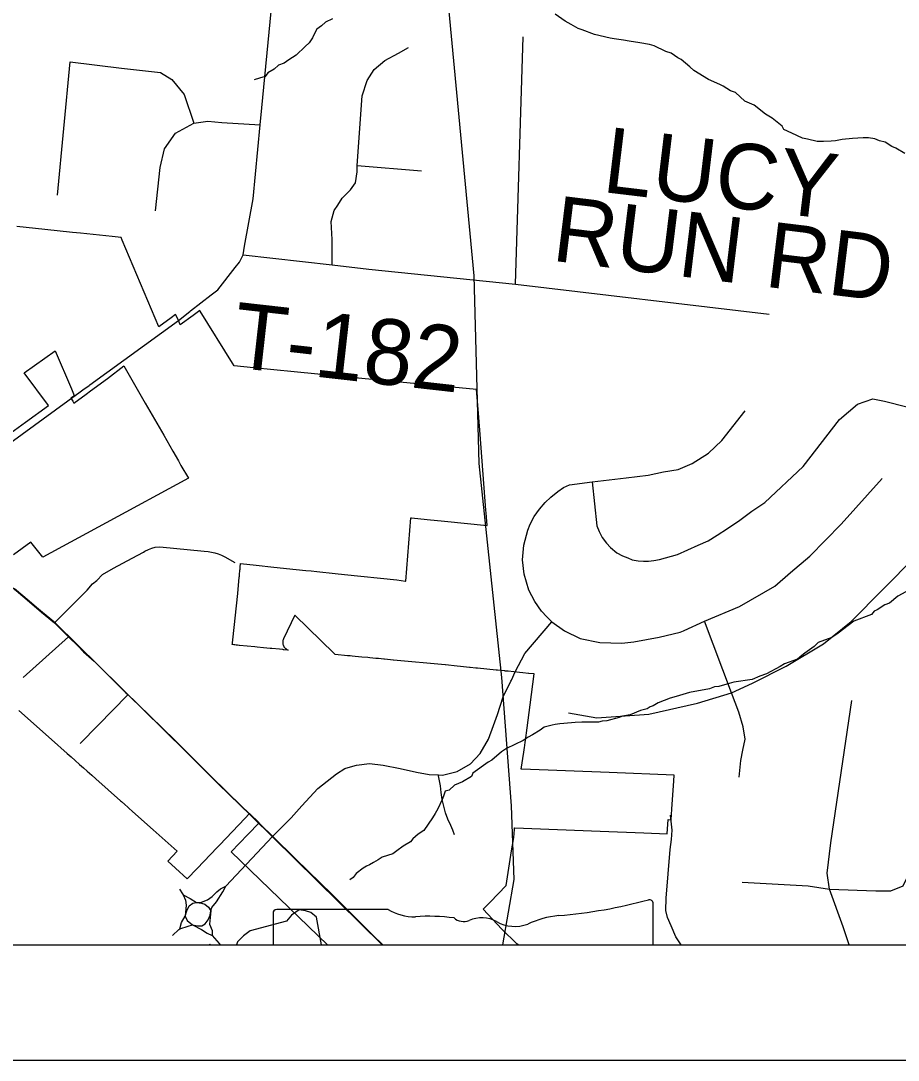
# Model space of a CAD drawing. Extents: x 0 to 34, y 0 to 22.
# Drawn here: x 2.613 to 3.374, y 14 to 14.902 of the extents above; entities that cross this region are included whole.
import ezdxf

# ---------------------------------------------------------------- set-up
doc = ezdxf.new("R2010")
doc.units = 0
for name, color, linetype in [('GM_X_City_Street', 7, 'Continuous'), ('GM_X_Corporation', 7, 'Continuous'), ('GM_X_County_Road', 7, 'Continuous'), ('GM_X_Minor_Lake', 7, 'Continuous'), ('GM_X_Minor_River', 7, 'Continuous'), ('GM_X_Rail_Line', 7, 'Continuous'), ('GM_X_State_Route', 7, 'Continuous'), ('GM_X_Township_Road', 7, 'Continuous'), ('GM_X_Township_Road_Text', 7, 'Continuous'), ('GM_X_Unincorporated_Text', 7, 'Continuous'), ('SH_Data', 7, 'Continuous')]:
    doc.layers.add(name, color=color, linetype=linetype)

msp = doc.modelspace()

# ---------------------------------------------------------------- linework, layer by layer
at = {"layer": 'GM_X_City_Street'}
msp.add_line((2.61532, 14.33202), (2.65464, 14.36727), dxfattribs=at)
at = {"layer": 'GM_X_Corporation'}
for points in [[(2.61152, 14.30346), (2.63996, 14.27817), (2.65355, 14.26609), (2.65684, 14.26316), (2.6603, 14.26009), (2.66421, 14.25661), (2.66766, 14.25354), (2.67075, 14.2508), (2.6747, 14.24729), (2.67838, 14.24401), (2.69964, 14.2251), (2.70042, 14.22441), (2.70331, 14.22184), (2.70601, 14.21944), (2.70685, 14.21869), (2.71009, 14.21581), (2.72812, 14.19978), (2.7488, 14.18138), (2.74083, 14.17279), (2.74737, 14.16663), (2.75738, 14.15721), (2.76615, 14.16639), (2.78359, 14.18464), (2.78381, 14.18487), (2.78565, 14.1868), (2.80756, 14.20972), (2.81153, 14.21387), (2.81155, 14.21389), (2.81981, 14.20583), (2.81979, 14.20581), (2.81001, 14.19576), (2.79551, 14.18084), (2.87906, 14.1), (3.04437, 14.1), (3.0434, 14.10096), (3.04339, 14.10096), (3.0304, 14.11377), (3.01404, 14.1311), (3.02007, 14.13723), (3.03408, 14.1515), (3.03881, 14.18174), (3.04062, 14.19331), (3.04116, 14.20016), (3.04127, 14.20152), (3.0416, 14.20151), (3.11549, 14.19866), (3.15335, 14.1972), (3.17359, 14.19642), (3.17439, 14.20882), (3.17722, 14.20863), (3.17782, 14.21782), (3.17941, 14.24237), (3.17973, 14.24733), (3.12346, 14.24951), (3.04773, 14.25243), (3.04701, 14.25246), (3.04936, 14.26732), (3.04999, 14.27129), (3.05021, 14.27311), (3.05022, 14.27319), (3.05032, 14.27397), (3.05043, 14.27491), (3.05045, 14.27512), (3.05052, 14.27564), (3.05055, 14.2759), (3.05055, 14.27591), (3.05055, 14.27591), (3.05074, 14.27734), (3.0522, 14.28836), (3.05482, 14.30828), (3.05836, 14.33505), (3.05762, 14.33512), (3.05358, 14.33553), (3.0535, 14.33554), (3.04841, 14.33606), (3.0455, 14.33635), (3.03587, 14.33734), (3.0358, 14.33735), (3.03578, 14.33735), (3.03576, 14.33736), (3.03574, 14.33736), (3.03568, 14.33736), (3.03565, 14.33737), (3.03561, 14.33737), (3.03461, 14.33747), (3.03406, 14.33753), (3.03343, 14.33759), (3.03296, 14.33764), (3.03227, 14.33771), (3.03227, 14.33771), (3.02999, 14.33794), (3.02654, 14.33829), (3.02527, 14.33842), (3.00906, 14.34007), (3.00779, 14.3402), (3.00283, 14.3407), (3.00238, 14.34075), (2.99458, 14.34154), (2.99456, 14.34154), (2.9917, 14.34192), (2.98139, 14.34288), (2.98102, 14.34292), (2.93642, 14.3471), (2.9363, 14.34711), (2.93607, 14.34713), (2.93375, 14.34735), (2.92856, 14.34783), (2.92851, 14.34784), (2.92805, 14.34788), (2.92343, 14.34832), (2.92094, 14.34855), (2.91594, 14.34902), (2.91417, 14.34918), (2.90879, 14.34969), (2.9031, 14.35022), (2.90048, 14.35047), (2.89884, 14.35062), (2.89846, 14.35066), (2.89845, 14.35066), (2.89821, 14.35068), (2.89736, 14.35076), (2.89714, 14.35078), (2.89642, 14.35085), (2.88578, 14.35184), (2.88491, 14.35269), (2.88489, 14.35271), (2.85074, 14.38596), (2.84102, 14.36558), (2.84087, 14.36523), (2.84073, 14.36488), (2.84062, 14.36452), (2.84052, 14.36415), (2.84044, 14.36378), (2.84038, 14.36341), (2.84034, 14.36303), (2.84032, 14.36265), (2.84032, 14.36227), (2.84034, 14.36189), (2.84039, 14.36152), (2.84045, 14.36114), (2.84053, 14.36077), (2.84063, 14.36041), (2.84074, 14.36005), (2.84088, 14.35969), (2.84104, 14.35935), (2.84121, 14.35901), (2.8414, 14.35868), (2.84161, 14.35837), (2.84184, 14.35806), (2.84208, 14.35777), (2.84233, 14.35749), (2.8426, 14.35722), (2.84286, 14.35699), (2.84289, 14.35697), (2.84289, 14.35697), (2.84318, 14.35674), (2.84349, 14.35651), (2.84381, 14.35631), (2.84442, 14.35598), (2.84511, 14.35566), (2.84505, 14.35566), (2.84126, 14.35603), (2.84122, 14.35604), (2.84112, 14.35605), (2.84105, 14.35605), (2.84054, 14.35611), (2.84049, 14.35611), (2.83754, 14.3564), (2.83749, 14.35641), (2.83094, 14.35705), (2.83089, 14.35706), (2.83087, 14.35706), (2.83081, 14.35706), (2.82956, 14.35719), (2.82952, 14.35719), (2.82375, 14.35776), (2.81826, 14.3583), (2.81616, 14.35851), (2.80288, 14.35982), (2.80288, 14.35982), (2.80287, 14.35982), (2.80284, 14.35982), (2.80282, 14.35982), (2.80265, 14.35984), (2.80261, 14.35984), (2.80124, 14.35998), (2.80119, 14.35998), (2.80076, 14.36003), (2.80071, 14.36003), (2.80038, 14.36006), (2.80034, 14.36007), (2.80009, 14.36009), (2.80005, 14.3601), (2.79892, 14.36021), (2.79887, 14.36021), (2.79846, 14.36025), (2.79842, 14.36026), (2.79822, 14.36028), (2.79817, 14.36028), (2.79787, 14.36031), (2.79782, 14.36031), (2.79658, 14.36044), (2.79658, 14.36048), (2.79659, 14.36056), (2.79669, 14.36152), (2.79671, 14.36166), (2.79671, 14.36167), (2.79671, 14.36169), (2.79687, 14.36321), (2.79693, 14.36378), (2.79702, 14.36464), (2.79702, 14.36466), (2.80127, 14.40482), (2.80264, 14.419), (2.80272, 14.4198), (2.80277, 14.42027), (2.80277, 14.42029), (2.80289, 14.42156), (2.80289, 14.42156), (2.80289, 14.42157), (2.8029, 14.42158), (2.80317, 14.42442), (2.80323, 14.42498), (2.80331, 14.42585), (2.80347, 14.42753), (2.80379, 14.4308), (2.81733, 14.42939), (2.83252, 14.4278), (2.85207, 14.42577), (2.86026, 14.4249), (2.86492, 14.42441), (2.86987, 14.42388), (2.88587, 14.42219), (2.89383, 14.42134), (2.93925, 14.41662), (2.9393, 14.41662), (2.9467, 14.41566), (2.94714, 14.4156), (2.94719, 14.4156), (2.95136, 14.47054), (2.95136, 14.47054), (2.9515, 14.47053), (2.95197, 14.47048), (2.95206, 14.47047), (2.96559, 14.46907), (2.98056, 14.46752), (3.01743, 14.4637), (3.01658, 14.47469), (3.0164, 14.47706), (3.01137, 14.54267), (3.00994, 14.56124), (3.00838, 14.58164), (2.92362, 14.58994), (2.85025, 14.59713), (2.81509, 14.60057), (2.79829, 14.60222), (2.79689, 14.60449), (2.76882, 14.64975), (2.76853, 14.65022), (2.76274, 14.64599), (2.75143, 14.63772), (2.74965, 14.64239), (2.74747, 14.64674), (2.74363, 14.64394), (2.7328, 14.63602), (2.70122, 14.71127), (2.70028, 14.71351), (2.69245, 14.71434), (2.66489, 14.71729), (2.65807, 14.71802), (2.63408, 14.72059), (2.60982, 14.72319)], [(2.59822, 14.53956), (2.61719, 14.55336), (2.63713, 14.56787), (2.61617, 14.59622), (2.64299, 14.61528), (2.64304, 14.61528), (2.65704, 14.58235), (2.65956, 14.57645), (2.6582, 14.57544), (2.65673, 14.57437), (2.6582, 14.57176), (2.65919, 14.57), (2.66981, 14.57774), (2.67356, 14.58047), (2.6736, 14.58047), (2.68843, 14.59129), (2.68848, 14.59129), (2.70246, 14.60232), (2.70263, 14.60242), (2.72119, 14.56999), (2.73713, 14.54213), (2.73714, 14.54211), (2.7451, 14.52821), (2.74988, 14.51986), (2.75211, 14.51596), (2.75849, 14.50481), (2.68721, 14.46601), (2.63243, 14.43625), (2.62189, 14.44944), (2.60692, 14.43841)], [(2.1, 14.1), (2.92709, 14.1), (2.91838, 14.10854), (2.88332, 14.1436), (2.85158, 14.17424), (2.83128, 14.19448), (2.78403, 14.24031), (2.74675, 14.27759), (2.70393, 14.3193), (2.67652, 14.34656), (2.66723, 14.35478), (2.66279, 14.35954), (2.6544, 14.3678), (2.64208, 14.37994), (2.63088, 14.38929), (2.62061, 14.39819), (2.60788, 14.40877)], [(2.60788, 14.40877), (2.62061, 14.39819), (2.63088, 14.38929), (2.64208, 14.37994), (2.6544, 14.3678), (2.66279, 14.35954), (2.66723, 14.35478), (2.67652, 14.34656), (2.70393, 14.3193), (2.74675, 14.27759), (2.78403, 14.24031), (2.83128, 14.19448), (2.85158, 14.17424), (2.88332, 14.1436), (2.91838, 14.10854), (2.92709, 14.1), (8.84304, 14.1)]]:
    msp.add_lwpolyline(points, dxfattribs=at)
at = {"layer": 'GM_X_County_Road'}
msp.add_line((2.52229, 14.47602), (2.66473, 14.57966), dxfattribs=at)
for points in [[(2.75963, 14.6495), (2.76038, 14.65011), (2.77826, 14.66395), (2.78395, 14.66831), (2.79917, 14.68772), (2.8027, 14.69218), (2.8059, 14.69855), (2.80724, 14.70611), (2.81482, 14.74724), (2.82071, 14.81123), (2.82208, 14.82597), (2.83027, 14.90961)], [(2.66473, 14.57966), (2.6671, 14.58138), (2.67241, 14.58525), (2.67317, 14.5858), (2.74982, 14.64157), (2.75963, 14.6495)]]:
    msp.add_lwpolyline(points, dxfattribs=at)
at = {"layer": 'GM_X_Minor_Lake'}
for p, q in [((2.77719, 14.10071), (2.7765, 14.1)), ((2.77775, 14.1), (2.77719, 14.10071))]:
    msp.add_line(p, q, dxfattribs=at)
msp.add_lwpolyline([(2.87387, 14.1), (2.86961, 14.1242), (2.86473, 14.12808), (2.86019, 14.12968), (2.85451, 14.13054), (2.84796, 14.12571), (2.84369, 14.12047), (2.81199, 14.11227), (2.80621, 14.10781), (2.80118, 14.10257), (2.80032, 14.1)], dxfattribs=at)
at = {"layer": 'GM_X_Minor_River'}
for points in [[(2.8834, 14.90326), (2.87726, 14.90032), (2.87379, 14.89734), (2.86994, 14.89437), (2.86838, 14.89173), (2.86601, 14.88683), (2.86328, 14.88232), (2.8598, 14.87933), (2.85208, 14.87186), (2.84554, 14.86779), (2.84169, 14.86482), (2.83672, 14.863), (2.83286, 14.85965), (2.82748, 14.85632), (2.82515, 14.85332), (2.82018, 14.85189), (2.8156, 14.85044)], [(3.27341, 14.81007), (3.26479, 14.81707), (3.25876, 14.8206), (3.24901, 14.82838), (3.24108, 14.83194), (3.23284, 14.83931), (3.22869, 14.8409), (3.22229, 14.84482), (3.21928, 14.84639), (3.20947, 14.85075), (3.19667, 14.85858), (3.1933, 14.86168), (3.1858, 14.8679), (3.18279, 14.86947), (3.17715, 14.87338), (3.17262, 14.87498), (3.16243, 14.87972), (3.15827, 14.88093), (3.14993, 14.8826), (3.14083, 14.8839), (3.1359, 14.88475), (3.12756, 14.88604), (3.12415, 14.88648), (3.11052, 14.88976), (3.09994, 14.89375), (3.09654, 14.89495), (3.09051, 14.89848), (3.08524, 14.90123), (3.0766, 14.90747)], [(3.37984, 14.78653), (3.37194, 14.79123), (3.36854, 14.79243), (3.36252, 14.79634), (3.3576, 14.79757), (3.35383, 14.79915), (3.34814, 14.80001), (3.34358, 14.80009), (3.33444, 14.79949), (3.3253, 14.79851), (3.31958, 14.79747), (3.31577, 14.79716), (3.30931, 14.79689), (3.30361, 14.79699), (3.29528, 14.79904), (3.29111, 14.79987), (3.28168, 14.80422), (3.27489, 14.80739), (3.27341, 14.81007)], [(3.38067, 14.40618), (3.37376, 14.4025), (3.36644, 14.39654), (3.36223, 14.39509), (3.3557, 14.39065), (3.35302, 14.38955), (3.35069, 14.38655), (3.33538, 14.38073), (3.3219, 14.37032), (3.31651, 14.36661), (3.30466, 14.36225), (3.30118, 14.35889), (3.29309, 14.35295), (3.2904, 14.35109), (3.28654, 14.34774), (3.27545, 14.34375), (3.27161, 14.34154), (3.25972, 14.33528), (3.25398, 14.3331), (3.24747, 14.33017), (3.23146, 14.32779), (3.22726, 14.32672)], [(3.22726, 14.32672), (3.21847, 14.32421), (3.21467, 14.3239), (3.21046, 14.32207), (3.19291, 14.31895), (3.18145, 14.31535), (3.1761, 14.31392), (3.16577, 14.30992), (3.16154, 14.30733), (3.15887, 14.30662), (3.15618, 14.30476), (3.15045, 14.30334), (3.14165, 14.29969), (3.13478, 14.29829), (3.1321, 14.2972), (3.12141, 14.29434), (3.11722, 14.29404), (3.11417, 14.29333), (3.09972, 14.2932), (3.09401, 14.29292), (3.09058, 14.2926), (3.08068, 14.29164), (3.07649, 14.29133), (3.07382, 14.29061), (3.06695, 14.28883), (3.06348, 14.28623), (3.05695, 14.28216), (3.05312, 14.28033), (3.04889, 14.27736), (3.03432, 14.27039), (3.03009, 14.26742), (3.02161, 14.26034), (3.01854, 14.25849), (3.00507, 14.24884), (3.00388, 14.2462), (2.9962, 14.24139), (2.9893, 14.23847), (2.98467, 14.23436), (2.98123, 14.23328), (2.97964, 14.22913), (2.97845, 14.2261), (2.9749, 14.21818), (2.97255, 14.21403), (2.9702, 14.21027), (2.96279, 14.19937), (2.9578, 14.19603), (2.95316, 14.19193), (2.95122, 14.1893), (2.94469, 14.18561), (2.9393, 14.18152), (2.93584, 14.17892), (2.92666, 14.17604), (2.9232, 14.17382), (2.91898, 14.17161), (2.91553, 14.16939), (2.91285, 14.1683), (2.91015, 14.16644), (2.904, 14.16198), (2.90128, 14.15861), (2.89858, 14.15637)]]:
    msp.add_lwpolyline(points, dxfattribs=at)
at = {"layer": 'GM_X_Rail_Line'}
for points in [[(2.79879, 17.13903), (2.8205, 17.01461), (2.83667, 16.75533), (2.86205, 16.4782), (2.87998, 16.38425), (2.946, 16.1063), (2.96807, 15.97749), (2.96317, 15.81684), (2.96042, 15.40669), (2.97141, 15.04765), (3.00596, 14.68036), (3.01023, 14.51763), (3.02993, 14.33209), (3.03825, 14.22063), (3.04073, 14.15661), (3.03083, 14.1)], [(2.92662, 14.1), (2.64317, 14.37918), (2.29707, 14.66316), (2.1, 14.8389)]]:
    msp.add_lwpolyline(points, dxfattribs=at)
at = {"layer": 'GM_X_State_Route'}
for points in [[(2.61111, 14.40576), (2.62084, 14.39766), (2.63112, 14.38877), (2.64231, 14.37941), (2.65464, 14.36727), (2.66302, 14.35901), (2.66747, 14.35426), (2.67675, 14.34604), (2.69714, 14.32577)], [(2.69714, 14.32577), (2.70416, 14.31877), (2.70592, 14.31707), (2.74698, 14.27707), (2.78426, 14.23979), (2.83151, 14.19395), (2.85181, 14.17372), (2.88355, 14.14308), (2.91861, 14.10802), (2.92679, 14.1)]]:
    msp.add_lwpolyline(points, dxfattribs=at)
at = {"layer": 'GM_X_Township_Road'}
for p, q in [((3.04208, 14.673), (3.04886, 14.88765)), ((2.90474, 14.77604), (2.96068, 14.77149)), ((2.79113, 14.15088), (2.83151, 14.19395)), ((2.75089, 14.14842), (2.75337, 14.14434)), ((2.74477, 14.10814), (2.75032, 14.1134))]:
    msp.add_line(p, q, dxfattribs=at)
for points in [[(2.88314, 14.68981), (2.88319, 14.71182), (2.88237, 14.72756), (2.88485, 14.73709), (2.88816, 14.74165), (2.8919, 14.74787), (2.89894, 14.75491), (2.9035, 14.76113), (2.90474, 14.77065), (2.90474, 14.77604), (2.9093, 14.83654), (2.91344, 14.8498), (2.91966, 14.85933), (2.92878, 14.86721), (2.94079, 14.87342), (2.94949, 14.87839)], [(2.64514, 14.7504), (2.6559, 14.86597), (2.70067, 14.86045), (2.73432, 14.85675), (2.74408, 14.85069), (2.75485, 14.83757), (2.76315, 14.81279)], [(2.72995, 14.73661), (2.73398, 14.7743), (2.73769, 14.79045), (2.74745, 14.80425), (2.76315, 14.81279), (2.77544, 14.81454), (2.7875, 14.81334), (2.82071, 14.81123)], [(2.8059, 14.69855), (2.88314, 14.68981), (2.91502, 14.6862), (3.04208, 14.673), (3.26201, 14.64703)], [(3.08823, 14.30136), (3.11273, 14.29701), (3.15779, 14.30018), (3.20008, 14.30967), (3.22933, 14.31876), (3.24751, 14.32706), (3.27676, 14.34168), (3.30917, 14.36105), (3.33328, 14.38041), (3.38869, 14.43659), (3.41707, 14.46935), (3.44867, 14.50572), (3.46806, 14.52982), (3.51457, 14.58714)], [(3.10854, 14.50169), (3.11278, 14.46353), (3.11462, 14.4585), (3.11742, 14.45337), (3.12105, 14.44852), (3.1246, 14.4446), (3.1301, 14.44022), (3.13495, 14.43751), (3.13943, 14.43565), (3.14335, 14.43415), (3.14848, 14.43313), (3.15314, 14.43285), (3.15743, 14.43285), (3.162, 14.43331), (3.16685, 14.43434), (3.18269, 14.43851), (3.20048, 14.44662), (3.20917, 14.45057), (3.21688, 14.45531), (3.22597, 14.46124), (3.23664, 14.46855), (3.24692, 14.47626), (3.25838, 14.48377), (3.29163, 14.51504), (3.32319, 14.55586), (3.33853, 14.56919), (3.35186, 14.57353), (3.36199, 14.57179), (3.38139, 14.56687)], [(3.0737, 14.38032), (3.06938, 14.38457), (3.0648, 14.38954), (3.05887, 14.39774), (3.05377, 14.40769), (3.04958, 14.42159), (3.04833, 14.43403), (3.04933, 14.44676), (3.05282, 14.4597), (3.05497, 14.46482), (3.05841, 14.47154), (3.06289, 14.47807), (3.06774, 14.48367), (3.07278, 14.48851), (3.07875, 14.49337), (3.08378, 14.49673), (3.089, 14.49906), (3.10854, 14.50169), (3.13796, 14.50504), (3.15711, 14.50734), (3.17049, 14.51034), (3.18318, 14.51242), (3.19541, 14.51749), (3.20949, 14.5265), (3.22103, 14.53757), (3.24133, 14.56318)], [(3.0737, 14.38032), (3.08467, 14.37251), (3.09811, 14.36579), (3.1153, 14.36243), (3.13427, 14.36184), (3.14475, 14.36282), (3.16668, 14.36697), (3.18492, 14.37135), (3.18774, 14.37241), (3.18834, 14.37269), (3.20598, 14.38081), (3.23644, 14.39346), (3.26688, 14.41124), (3.28071, 14.4231), (3.29731, 14.43733), (3.32458, 14.465), (3.36016, 14.50452)], [(2.64231, 14.37941), (2.67084, 14.40779), (2.67544, 14.41315), (2.67912, 14.41607), (2.68418, 14.42144), (2.69354, 14.42665), (2.70964, 14.43554), (2.71946, 14.44076), (2.72075, 14.44164), (2.72385, 14.44303), (2.72675, 14.44408), (2.72977, 14.44487), (2.73372, 14.44539), (2.77225, 14.44158), (2.77554, 14.44119), (2.77857, 14.44079), (2.78146, 14.44013), (2.78448, 14.43921), (2.78725, 14.43803), (2.79013, 14.43674), (2.79893, 14.43174)], [(2.90123, 14.25514), (2.90422, 14.25603), (2.91566, 14.2575), (2.92747, 14.25603), (2.94224, 14.25308), (2.95626, 14.24975), (2.96733, 14.24791), (2.97531, 14.24739), (2.97878, 14.24717), (2.99164, 14.25036), (3.00304, 14.2572), (3.01153, 14.26611), (3.01864, 14.27854), (3.02307, 14.29035), (3.02639, 14.29995), (3.03156, 14.31508), (3.0382, 14.32874), (3.03861, 14.32964), (3.04189, 14.33686), (3.05027, 14.35278), (3.0737, 14.38032)], [(3.23604, 14.24563), (3.23763, 14.25986), (3.23921, 14.26895), (3.24118, 14.27844), (3.23961, 14.28911), (3.23565, 14.30176), (3.22933, 14.31876), (3.20598, 14.38081)], [(3.2386, 14.15445), (3.29585, 14.1513), (3.31444, 14.14844), (3.35453, 14.14701), (3.36769, 14.14701), (3.37828, 14.1513), (3.38229, 14.1596), (3.38373, 14.17306), (3.40462, 14.34195)], [(2.66478, 14.27484), (2.68031, 14.29068), (2.7056, 14.31675)], [(3.33153, 14.1), (3.32612, 14.1156), (3.31444, 14.14844), (3.31245, 14.16218), (3.31552, 14.18862), (3.33363, 14.31189)], [(2.83151, 14.19395), (2.84752, 14.21036), (2.85697, 14.22059), (2.87063, 14.23573), (2.88687, 14.24827), (2.89425, 14.25308), (2.90123, 14.25514)], [(2.98929, 14.19556), (2.98773, 14.19945), (2.98602, 14.20366), (2.9836, 14.2091), (2.98154, 14.21468), (2.97986, 14.22039), (2.97855, 14.22619), (2.97762, 14.23207), (2.97708, 14.23799), (2.97537, 14.2468), (2.97531, 14.24739)], [(3.18568, 14.1), (3.18122, 14.10712), (3.17702, 14.11648), (3.1738, 14.12375), (3.17234, 14.12988), (3.17283, 14.14069), (3.17621, 14.18264), (3.17734, 14.19152), (3.17799, 14.19959), (3.17654, 14.21266)], [(2.75032, 14.1134), (2.75101, 14.11406), (2.75825, 14.11636), (2.76219, 14.11735), (2.76647, 14.11669), (2.77009, 14.11669), (2.77304, 14.11833), (2.77568, 14.12162), (2.77732, 14.12589), (2.77798, 14.12951), (2.77896, 14.13247), (2.78291, 14.1374), (2.7885, 14.14595), (2.79113, 14.15088)], [(2.75101, 14.11406), (2.75262, 14.11932), (2.75582, 14.12499), (2.7573, 14.12968), (2.75928, 14.13387), (2.76224, 14.13609), (2.76544, 14.13683), (2.76988, 14.13707), (2.77506, 14.13905), (2.779, 14.14201), (2.7832, 14.14595), (2.7864, 14.14866), (2.79113, 14.15088)], [(2.75337, 14.14434), (2.75387, 14.14353), (2.75607, 14.1388), (2.75656, 14.13436), (2.75582, 14.12499), (2.75751, 14.12117), (2.76219, 14.11735), (2.76988, 14.1134), (2.77481, 14.11019), (2.779, 14.10822)], [(2.75387, 14.14353), (2.76008, 14.14028), (2.76544, 14.13683), (2.76987, 14.13618), (2.77271, 14.13526), (2.7761, 14.13285), (2.77798, 14.12951), (2.77678, 14.11809), (2.779, 14.11241), (2.779, 14.10822)], [(2.779, 14.10822), (2.78517, 14.10132), (2.78601, 14.1)]]:
    msp.add_lwpolyline(points, dxfattribs=at)
at = {"layer": 'GM_X_Unincorporated_Text'}
msp.add_line((2.93168, 14.13083), (2.83509, 14.13083), dxfattribs=at)
msp.add_lwpolyline([(2.83191, 14.12735), (2.83191, 14.1), (3.1615, 14.1), (3.1615, 14.13597)], dxfattribs=at)
for centre, major_axis, start_param, end_param in [((3.04409, 14.40366), (0.34952, 0), 4.814394, 5.042369), ((3.15784, 14.13622), (0.00367, 0), 6.197627, 7.989034), ((2.83569, 14.12781), (0.00382, 0), 1.727492, 3.291633), ((2.95466, 14.15406), (0.03703, 0), 4.042888, 4.731792), ((2.96694, 14.01848), (0.13295, 0), 1.404758, 1.657859), ((2.99713, 14.12885), (0.01068, 0), 3.836095, 5.185415), ((3.01281, 14.10572), (0.02221, 0), 0.950623, 2.079405), ((3.04148, 14.13744), (0.02672, 0), 4.08156, 5.145723), ((3.08868, 14.0697), (0.07032, 0), 1.699012, 2.107814)]:
    msp.add_ellipse(centre, major_axis=major_axis, ratio=0.8, start_param=start_param, end_param=end_param, dxfattribs=at)
at = {"layer": 'SH_Data'}
for p, q in [((2.1, 14.1), (8.9, 14.1)), ((2, 14), (9, 14))]:
    msp.add_line(p, q, dxfattribs=at)

# ---------------------------------------------------------------- texts
at = {"layer": 'GM_X_Township_Road_Text'}
for s, rotation, p in [('LUCY', 353.15707, (3.11636, 14.75321)), ('RUN RD', 353.03341, (3.07263, 14.69364)), ('T-182', 353.56993, (2.79508, 14.60123))]:
    msp.add_text(s, height=0.056818, rotation=rotation, dxfattribs=at).set_placement(p)

doc.saveas('drawing.dxf')
